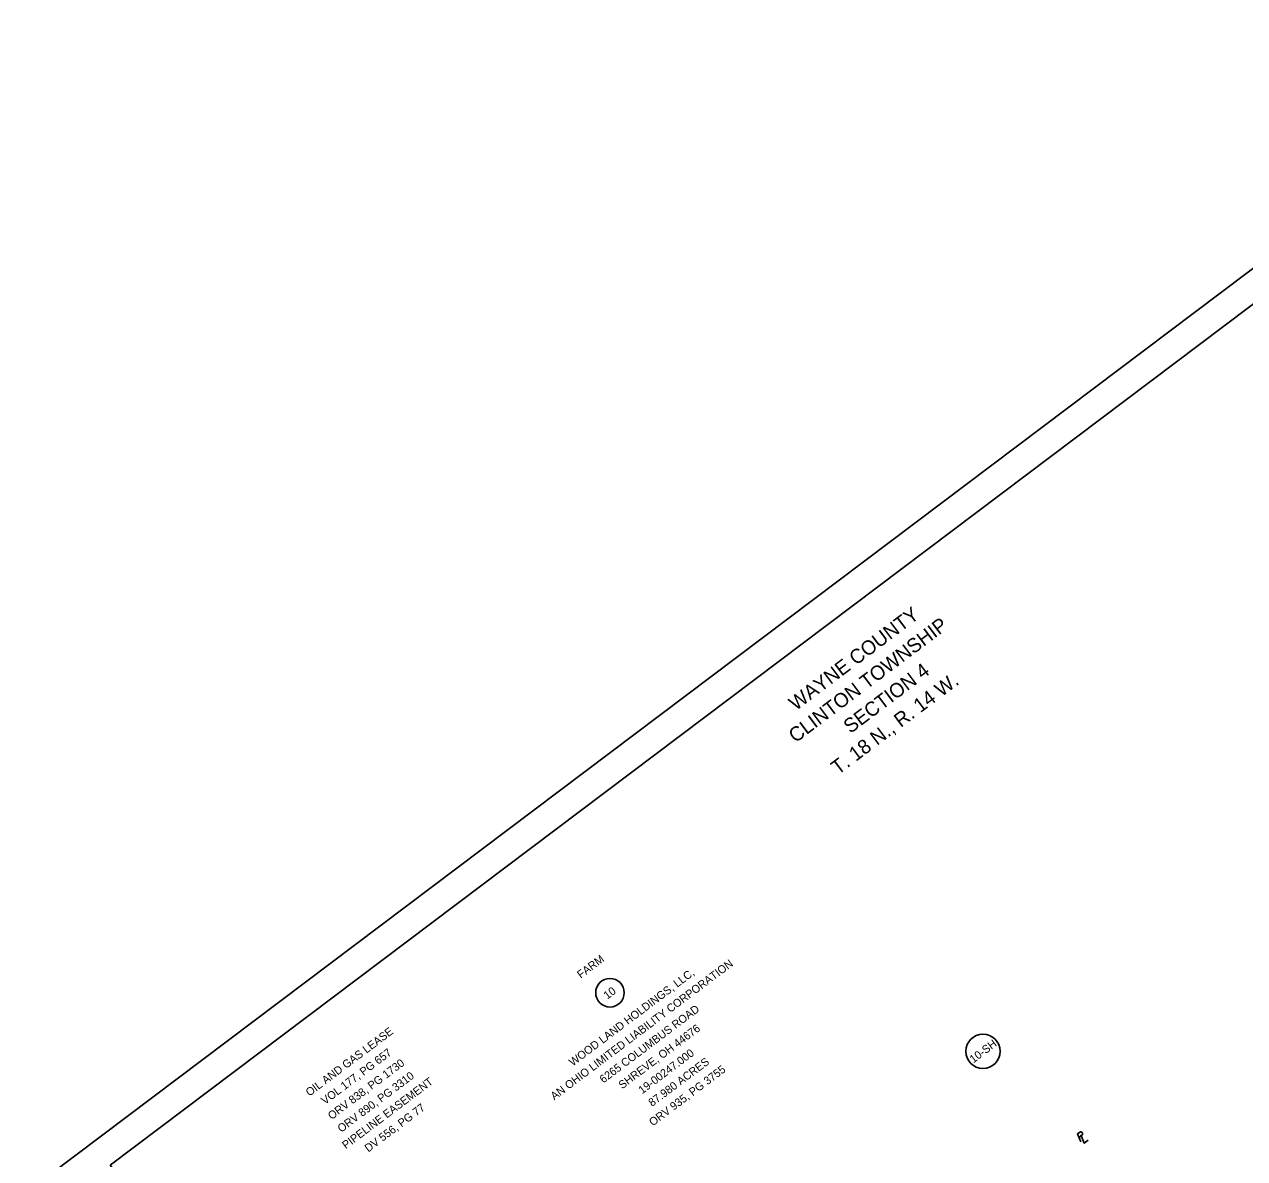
# Model space of a CAD drawing. Extents: x 120088 to 120896, y 463169 to 463930.
# Drawn here: x 120088 to 120514.9, y 463533.3 to 463930 of the extents above; entities that cross this region are included whole.
import ezdxf

# ---------------------------------------------------------------- set-up
doc = ezdxf.new("R2010")
doc.units = 0
for name, color, linetype in [('RD_X_Cells', 7, 'Continuous'), ('RD_X_RR_Cells', 7, 'Continuous'), ('SV_P_Mon_Cells_Set', 7, 'Continuous'), ('SV_X_Mon_Cells_Found', 7, 'Continuous'), ('SV_X_Shot_Marker', 7, 'Continuous')]:
    doc.layers.add(name, color=color, linetype=linetype)

msp = doc.modelspace()

# ---------------------------------------------------------------- linework, layer by layer
at = {"layer": 'RD_X_Cells'}
msp.add_lwpolyline([(120352.65, 463169.48), (120895.84, 463578.55), (120631.15, 463930.03), (120087.95, 463520.96)], close=True, dxfattribs=at)
at = {"layer": 'SV_P_Mon_Cells_Set'}
for centre, radius in [((120292.83, 463591.33), 5), ((120423.33, 463570.85), 6)]:
    msp.add_circle(centre, radius, dxfattribs=at)
at = {"layer": 'SV_X_Mon_Cells_Found'}
msp.add_lwpolyline([(120117.93, 463531.02), (120629.17, 463916.03), (120881.84, 463580.52), (120370.6, 463195.51)], close=True, dxfattribs=at)
at = {"layer": 'SV_X_Shot_Marker'}
for p, q in [((120456.92, 463540.64), (120457.95, 463541.42)), ((120457.93, 463540.63), (120457.93, 463540.63))]:
    msp.add_line(p, q, dxfattribs=at)
for points in [[(120457.54, 463539.12), (120456.38, 463541.96), (120457.2, 463542.58)], [(120457.57, 463541.56), (120458.71, 463538.72), (120460.11, 463539.77)]]:
    msp.add_lwpolyline(points, dxfattribs=at)
msp.add_arc((120457.53, 463541.97), 0.69, 307.4541, 118.3112, dxfattribs=at)

# ---------------------------------------------------------------- texts
at = {"layer": 'RD_X_RR_Cells'}
for s, p in [('               WAYNE COUNTY               ', (120335.57, 463673.01)), ('             CLINTON TOWNSHIP             ', (120338.44, 463663.99)), ('                 SECTION 4                ', (120351.7, 463662.79)), ('            T. 18 N., R. 14 W.            ', (120354.8, 463653.94))]:
    msp.add_text(s, height=5, rotation=36.9831, dxfattribs=at).set_placement(p)
at = {"layer": 'SV_P_Mon_Cells_Set'}
for s, p in [('FARM', (120282.63, 463596.17)), ('AN OHIO LIMITED LIABILITY CORPORATION', (120273.36, 463553.64)), ('WOOD LAND HOLDINGS, LLC,', (120279.8, 463565.5)), ('10', (120291.89, 463588.87)), ('6265 COLUMBUS ROAD', (120290.51, 463559.54)), ('OIL AND GAS LEASE', (120187.68, 463554.95)), ('SHREVE, OH 44676', (120297.11, 463557.5)), ('10-SH', (120419.96, 463566.57)), ('VOL 177, PG 657', (120193.11, 463552.03)), ('19-00247.000', (120304.1, 463555.76)), ('ORV 838, PG 1730', (120195.44, 463546.77)), ('87.980 ACRES', (120307.58, 463551.36)), ('ORV 935, PG 3755', (120307.81, 463544.53)), ('ORV 890, PG 3310', (120198.81, 463542.3)), ('PIPELINE EASEMENT', (120200.44, 463536.52)), ('DV 556, PG 77', (120208.28, 463535.41))]:
    msp.add_text(s, height=2.8, rotation=36.9831, dxfattribs=at).set_placement(p)

doc.saveas('drawing.dxf')
